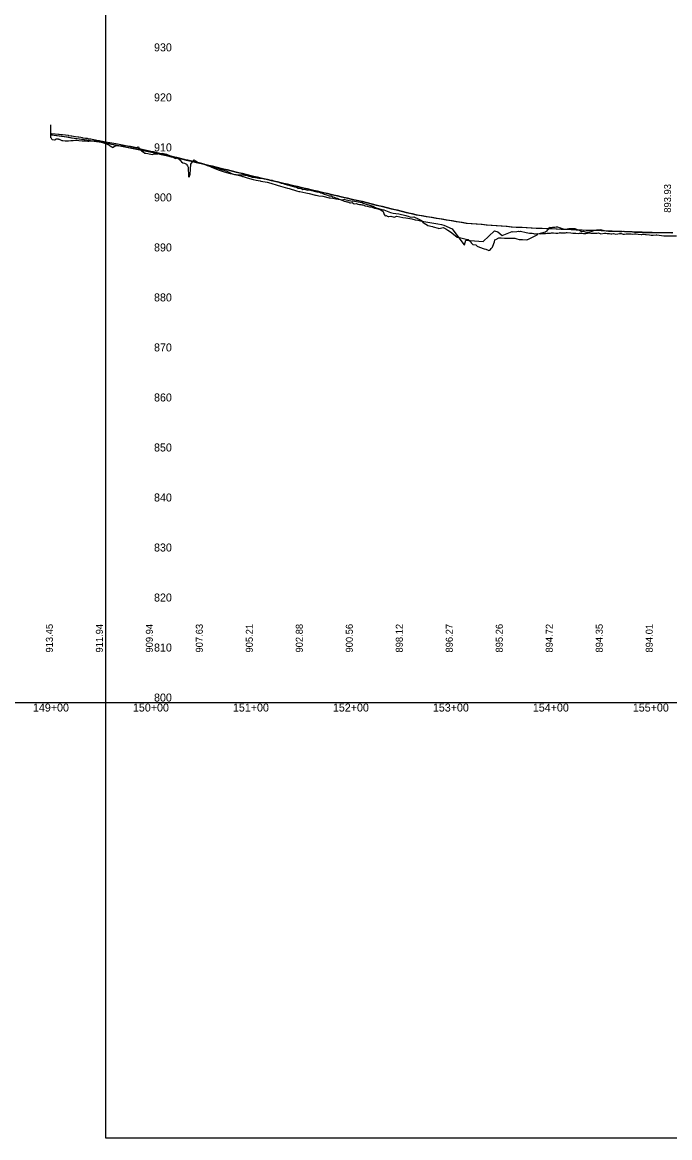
# Model space of a CAD drawing. Extents: x 1475774 to 1484571, y 1098511 to 1113011.
# Drawn here: x 1477639 to 1478287, y 1103076 to 1104191 of the extents above; entities that cross this region are included whole.
import ezdxf

# ---------------------------------------------------------------- set-up
doc = ezdxf.new("R2010")
doc.units = 0
for name, color, linetype in [('RD_DDB_ElevTX', 7, 'Continuous'), ('RD_DDB_PointTX', 7, 'Continuous'), ('RD_DDB_Profile_EX', 7, 'Continuous'), ('RD_DDB_Profile_Lbl', 7, 'Continuous'), ('RD_DDB_StaTX', 7, 'Continuous'), ('RD_DDB_StripGrade', 7, 'Continuous'), ('RD_GPK_Profile_Cell', 7, 'Continuous'), ('RD_Sketch2', 7, 'Continuous'), ('RD_Sketch3', 7, 'Continuous'), ('RD_Sketch5', 7, 'Continuous')]:
    doc.layers.add(name, color=color, linetype=linetype)

msp = doc.modelspace()

# ---------------------------------------------------------------- linework, layer by layer
at = {"layer": 'RD_DDB_PointTX'}
for points in [[(1477668.3, 1104079), (1477669.4, 1104078.9), (1477674.4, 1104078.1), (1477679.4, 1104077.4), (1477684.4, 1104076.7), (1477689.4, 1104075.9), (1477694.4, 1104075.2), (1477699.4, 1104074.4), (1477704.4, 1104073.7), (1477709.4, 1104072.9), (1477714.4, 1104072.2), (1477719.4, 1104071.4), (1477724.4, 1104070.4), (1477729.4, 1104069.4), (1477734.4, 1104068.4), (1477739.4, 1104067.4), (1477744.4, 1104066.4), (1477749.4, 1104065.4), (1477754.4, 1104064.4), (1477759.4, 1104063.4), (1477764.4, 1104062.4), (1477769.4, 1104061.5), (1477774.4, 1104060.4), (1477779.4, 1104059.2), (1477784.4, 1104058.1), (1477789.4, 1104056.9), (1477794.4, 1104055.8), (1477799.4, 1104054.6), (1477804.4, 1104053.4), (1477809.4, 1104052.3), (1477814.4, 1104051.1), (1477819.4, 1104050), (1477824.4, 1104048.8), (1477829.4, 1104047.6), (1477834.4, 1104046.4), (1477839.4, 1104045.2), (1477844.4, 1104044), (1477849.4, 1104042.7), (1477854.4, 1104041.5), (1477859.4, 1104040.3), (1477864.4, 1104039.1), (1477869.4, 1104037.9), (1477874.4, 1104036.7), (1477879.4, 1104035.5), (1477884.4, 1104034.4), (1477889.4, 1104033.2), (1477894.4, 1104032), (1477899.4, 1104030.9), (1477904.4, 1104029.7), (1477909.4, 1104028.5), (1477914.4, 1104027.4), (1477919.4, 1104026.2), (1477924.4, 1104025), (1477929.4, 1104023.9), (1477934.4, 1104022.7), (1477939.4, 1104021.6), (1477944.4, 1104020.4), (1477949.4, 1104019.2), (1477954.4, 1104018.1), (1477959.4, 1104016.9), (1477964.4, 1104015.8), (1477969.4, 1104014.6), (1477974.4, 1104013.5), (1477979.4, 1104012.3), (1477984.4, 1104011.1), (1477989.4, 1104009.9), (1477994.4, 1104008.6), (1477999.4, 1104007.4), (1478004.4, 1104006.2), (1478009.4, 1104004.9), (1478014.4, 1104003.7), (1478019.4, 1104002.5), (1478024.4, 1104001.2), (1478029.4, 1104000), (1478034.4, 1103998.9), (1478039.4, 1103998.1), (1478044.4, 1103997.2), (1478049.4, 1103996.4), (1478054.4, 1103995.5), (1478059.4, 1103994.7), (1478064.4, 1103993.8), (1478069.4, 1103993), (1478074.4, 1103992.1), (1478079.4, 1103991.3), (1478084.4, 1103990.6), (1478089.4, 1103990.2), (1478094.4, 1103989.8), (1478099.4, 1103989.3), (1478104.4, 1103988.9), (1478109.4, 1103988.5), (1478114.4, 1103988.1), (1478119.4, 1103987.7), (1478124.4, 1103987.3), (1478129.4, 1103986.9), (1478134.4, 1103986.6), (1478139.4, 1103986.3), (1478144.4, 1103986.1), (1478149.4, 1103985.9), (1478154.4, 1103985.6), (1478159.4, 1103985.4), (1478164.4, 1103985.2)], [(1478164.4, 1103985.2), (1478169.4, 1103985), (1478174.4, 1103984.7), (1478179.4, 1103984.5), (1478184.4, 1103984.3), (1478189.4, 1103984.1), (1478194.4, 1103983.9), (1478199.4, 1103983.8), (1478204.4, 1103983.6), (1478209.4, 1103983.4), (1478214.4, 1103983.3), (1478219.4, 1103983.1), (1478224.4, 1103982.9), (1478229.4, 1103982.8), (1478234.4, 1103982.6), (1478239.4, 1103982.4), (1478244.4, 1103982.2), (1478249.4, 1103982.1), (1478254.4, 1103981.9), (1478259.4, 1103981.7), (1478264.4, 1103981.5), (1478269.4, 1103981.4), (1478274.4, 1103981.2), (1478279.4, 1103981.1), (1478284.4, 1103981), (1478289.4, 1103980.9)]]:
    msp.add_lwpolyline(points, dxfattribs=at)
at = {"layer": 'RD_DDB_Profile_EX'}
for points in [[(1477668.3, 1104078.9), (1477668.5, 1104078.9), (1477673.5, 1104078.1), (1477678.5, 1104077.4), (1477683.5, 1104076.7), (1477688.5, 1104075.9), (1477693.5, 1104075.2), (1477698.5, 1104074.4), (1477703.5, 1104073.7), (1477708.5, 1104072.9), (1477713.5, 1104072.2), (1477718.5, 1104071.4), (1477723.5, 1104070.4), (1477728.5, 1104069.4), (1477733.5, 1104068.4), (1477738.5, 1104067.4), (1477743.5, 1104066.4), (1477748.5, 1104065.4), (1477753.5, 1104064.4), (1477758.5, 1104063.4), (1477763.5, 1104062.4), (1477768.5, 1104061.5), (1477773.5, 1104060.4), (1477778.5, 1104059.2), (1477783.5, 1104058.1), (1477788.5, 1104056.9), (1477793.5, 1104055.8), (1477798.5, 1104054.6), (1477803.5, 1104053.4), (1477808.5, 1104052.3), (1477813.5, 1104051.1), (1477818.5, 1104050), (1477823.5, 1104048.8), (1477828.5, 1104047.6), (1477833.5, 1104046.4), (1477838.5, 1104045.2), (1477843.5, 1104044), (1477848.5, 1104042.7), (1477853.5, 1104041.5), (1477858.5, 1104040.3), (1477863.5, 1104039.1), (1477868.5, 1104037.9), (1477873.5, 1104036.7), (1477878.5, 1104035.5), (1477883.5, 1104034.4), (1477888.5, 1104033.2), (1477893.5, 1104032), (1477898.5, 1104030.9), (1477903.5, 1104029.7), (1477908.5, 1104028.5), (1477913.5, 1104027.4), (1477918.5, 1104026.2), (1477923.5, 1104025), (1477928.5, 1104023.9), (1477933.5, 1104022.7), (1477938.5, 1104021.6), (1477943.5, 1104020.4), (1477948.5, 1104019.2), (1477953.5, 1104018.1), (1477958.5, 1104016.9), (1477963.5, 1104015.8), (1477968.5, 1104014.6), (1477973.5, 1104013.5), (1477978.5, 1104012.3), (1477983.5, 1104011.1), (1477988.5, 1104009.9), (1477993.5, 1104008.6), (1477998.5, 1104007.4), (1478003.5, 1104006.2), (1478008.5, 1104004.9), (1478013.5, 1104003.7), (1478018.5, 1104002.5), (1478023.5, 1104001.2), (1478028.5, 1104000), (1478033.5, 1103998.9), (1478038.5, 1103998.1), (1478043.5, 1103997.2), (1478048.5, 1103996.4), (1478053.5, 1103995.5), (1478058.5, 1103994.7), (1478063.5, 1103993.8), (1478068.5, 1103993), (1478073.5, 1103992.1), (1478078.5, 1103991.3), (1478083.5, 1103990.6), (1478088.5, 1103990.2), (1478093.5, 1103989.8), (1478098.5, 1103989.3), (1478103.5, 1103988.9), (1478108.5, 1103988.5), (1478113.5, 1103988.1), (1478118.5, 1103987.7), (1478123.5, 1103987.3), (1478128.5, 1103986.9), (1478133.5, 1103986.6), (1478138.5, 1103986.3), (1478143.5, 1103986.1), (1478148.5, 1103985.9), (1478153.5, 1103985.6), (1478158.5, 1103985.4), (1478163.5, 1103985.2)], [(1478163.5, 1103985.2), (1478168.5, 1103985), (1478173.5, 1103984.7), (1478178.5, 1103984.5), (1478183.5, 1103984.3), (1478188.5, 1103984.1), (1478193.5, 1103983.9), (1478198.5, 1103983.8), (1478203.5, 1103983.6), (1478208.5, 1103983.4), (1478213.5, 1103983.3), (1478218.5, 1103983.1), (1478223.5, 1103982.9), (1478228.5, 1103982.8), (1478233.5, 1103982.6), (1478238.5, 1103982.4), (1478243.5, 1103982.2), (1478248.5, 1103982.1), (1478253.5, 1103981.9), (1478258.5, 1103981.7), (1478263.5, 1103981.5), (1478268.5, 1103981.4), (1478273.5, 1103981.2), (1478278.5, 1103981.1), (1478283.5, 1103981), (1478288.5, 1103980.9)]]:
    msp.add_lwpolyline(points, dxfattribs=at)
at = {"layer": 'RD_GPK_Profile_Cell'}
msp.add_line((1477571, 1103511.2), (1484571, 1103511.2), dxfattribs=at)
at = {"layer": 'RD_Sketch2'}
msp.add_lwpolyline([(1477667.5, 1104080.2), (1477668, 1104080.2), (1477668.8, 1104080.1), (1477672.2, 1104079.8), (1477675.6, 1104079.4), (1477676.2, 1104079.4), (1477677.9, 1104079.2), (1477679, 1104079.1), (1477679.6, 1104079.1), (1477682.5, 1104078.7), (1477685.4, 1104078.3), (1477685.8, 1104078.2), (1477688.4, 1104077.8), (1477689.1, 1104077.7), (1477690.8, 1104077.3), (1477692.5, 1104077.1), (1477695.2, 1104076.6), (1477695.9, 1104076.6), (1477698, 1104076.3), (1477699.3, 1104076.1), (1477700, 1104075.9), (1477702.7, 1104075.5), (1477703.2, 1104075.4), (1477704.3, 1104075.3), (1477706.1, 1104074.9), (1477708.1, 1104074.6), (1477709.4, 1104074.3), (1477712.8, 1104073.7), (1477714.1, 1104073.5), (1477716.2, 1104073.1), (1477717.2, 1104072.9), (1477719.6, 1104072.5), (1477723, 1104071.9), (1477723.4, 1104071.8), (1477726.3, 1104071.2), (1477726.9, 1104071.1), (1477733.1, 1104070), (1477734.5, 1104069.8), (1477741.3, 1104068.3), (1477744.4, 1104067.8), (1477751.6, 1104066.2), (1477753.6, 1104065.7), (1477756.7, 1104065.1), (1477759.4, 1104064.4), (1477766.8, 1104062.7), (1477768, 1104062.5), (1477770.5, 1104062), (1477778, 1104060.2), (1477778.9, 1104060), (1477783.1, 1104059), (1477785.3, 1104058.3), (1477793.1, 1104056.5), (1477793.8, 1104056.3), (1477801.3, 1104054.5), (1477804, 1104053.9), (1477805.1, 1104053.6), (1477811.7, 1104052), (1477812.1, 1104052), (1477812.7, 1104051.9), (1477813.3, 1104051.8), (1477814, 1104051.6), (1477814.8, 1104051.4), (1477820.9, 1104049.6), (1477821.6, 1104049.4), (1477822.5, 1104049.1), (1477824.5, 1104048.2), (1477826.7, 1104047.5), (1477827.1, 1104047.4), (1477827.4, 1104047.4), (1477827.7, 1104047.4), (1477830.3, 1104046.8), (1477830.7, 1104046.7), (1477831.4, 1104046.4), (1477832.4, 1104046.2), (1477833.5, 1104045.8), (1477834.7, 1104045.4), (1477836.5, 1104044.9), (1477837.5, 1104044.5), (1477838.5, 1104044.2), (1477839.7, 1104043.7), (1477840.9, 1104043.3), (1477841.2, 1104043.4), (1477841.6, 1104043.3), (1477842, 1104043), (1477842.9, 1104042.7), (1477843.9, 1104042.4), (1477845.5, 1104041.8), (1477847, 1104041), (1477848.1, 1104040.5), (1477848.7, 1104040.2), (1477850.8, 1104039.4), (1477851.8, 1104039.2), (1477853.5, 1104039), (1477855.8, 1104038.9), (1477857.8, 1104038.7), (1477859.3, 1104038.9), (1477860, 1104038.8), (1477860.8, 1104038.7), (1477862.1, 1104038.4), (1477863.1, 1104038.3), (1477864.2, 1104038.1), (1477865.9, 1104037.5), (1477866.4, 1104037.4), (1477866.8, 1104037.4), (1477869.5, 1104036.6), (1477870.5, 1104036.4), (1477870.9, 1104036.3), (1477872.8, 1104036), (1477874.3, 1104035.7), (1477875.9, 1104035.4), (1477878, 1104035.3), (1477879.3, 1104035.4), (1477881, 1104035), (1477881.4, 1104034.9), (1477881.7, 1104034.8), (1477883.5, 1104034.5), (1477886, 1104033.9), (1477887.8, 1104033.6), (1477889.2, 1104033.3), (1477890, 1104033.2), (1477891, 1104032.8), (1477892.1, 1104032.4), (1477892.9, 1104032.2), (1477894.3, 1104032), (1477896.1, 1104031.3), (1477896.7, 1104031.1), (1477898.5, 1104030.6), (1477900.7, 1104030.1), (1477901.1, 1104029.9), (1477904.2, 1104028.9), (1477906.1, 1104028.3), (1477907.1, 1104028.2), (1477907.9, 1104027.9), (1477909.3, 1104027.6), (1477911.6, 1104026.8), (1477913.6, 1104026.3), (1477915.4, 1104025.6), (1477916.2, 1104025.5), (1477917.9, 1104025.2), (1477919.1, 1104024.7), (1477920, 1104024.2), (1477921.2, 1104024.3), (1477922.8, 1104024), (1477924.3, 1104023.5), (1477926.6, 1104023.7), (1477928.6, 1104023), (1477930.3, 1104022.8), (1477931.3, 1104022.6), (1477934, 1104021.9), (1477935, 1104021.8), (1477936.3, 1104021.5), (1477937.2, 1104021.2), (1477937.8, 1104020.9), (1477939.3, 1104020.4), (1477941.5, 1104019.6), (1477943.6, 1104018.9), (1477945.3, 1104018.1), (1477946.4, 1104017.8), (1477947.9, 1104017.7), (1477949, 1104017.3), (1477950, 1104016.9), (1477951.4, 1104016.3), (1477952.2, 1104016), (1477952.7, 1104015.8), (1477954.3, 1104015.3), (1477956.5, 1104014.3), (1477960.2, 1104013.1), (1477960.7, 1104012.8), (1477961.5, 1104012.5), (1477962.9, 1104012.2), (1477963.9, 1104011.8), (1477965, 1104011.7), (1477966.5, 1104011), (1477967.2, 1104010.9), (1477967.7, 1104010.9), (1477969.3, 1104011), (1477971.5, 1104009.9), (1477973.6, 1104010.1), (1477975.1, 1104009.6), (1477976.6, 1104009.2), (1477977.9, 1104009.1), (1477978.9, 1104008.8), (1477980, 1104008.8), (1477981.6, 1104008), (1477982.2, 1104007.8), (1477982.6, 1104007.7), (1477984.3, 1104007.6), (1477986.6, 1104006.7), (1477988.6, 1104006.7), (1477990.1, 1104006), (1477991.7, 1104005.6), (1477993.6, 1104005.1), (1477994, 1104005), (1477995.9, 1104004.4), (1477998, 1104003.8), (1478000.4, 1104002.1), (1478001.3, 1103999.1), (1478002.3, 1103997.8), (1478003.8, 1103998.1), (1478004.4, 1103997.6), (1478005.3, 1103997.2), (1478006.2, 1103997), (1478008.1, 1103997.3), (1478011.4, 1103996.5), (1478014, 1103997.3), (1478020.1, 1103996.1), (1478023, 1103995.9), (1478029.2, 1103994.7), (1478032.4, 1103993.8), (1478032.8, 1103993.7), (1478035.2, 1103993.3), (1478039, 1103992.3), (1478045.2, 1103991.3), (1478049, 1103990.8), (1478055.2, 1103989.8), (1478058.8, 1103989), (1478061.2, 1103988.6), (1478069.5, 1103984.9), (1478081, 1103969), (1478081.7, 1103968.8), (1478083, 1103973.6), (1478100.3, 1103972.1), (1478111.8, 1103982.7), (1478115, 1103981.9), (1478119.5, 1103978), (1478129.3, 1103982.2), (1478129.8, 1103981.9), (1478134, 1103982.1), (1478135.6, 1103982.4), (1478136.9, 1103982.2), (1478137.9, 1103982.4), (1478143.3, 1103981.2), (1478146.8, 1103980.3), (1478147.1, 1103980.3), (1478147.6, 1103980.3), (1478149.4, 1103980.4), (1478150.8, 1103980.1), (1478151.6, 1103979.9), (1478152.7, 1103979.8), (1478154.5, 1103980.1), (1478158.2, 1103979.7), (1478160.2, 1103980.2), (1478162, 1103980), (1478162.3, 1103980.1), (1478162.8, 1103980), (1478164.5, 1103980.3), (1478165.7, 1103980.3), (1478166.6, 1103980.5), (1478167.8, 1103980.5), (1478168.7, 1103980.9), (1478169.4, 1103980.9), (1478170.9, 1103980.9), (1478173.2, 1103980.3), (1478175.2, 1103980.6), (1478176.9, 1103980.9), (1478177.3, 1103981), (1478177.9, 1103980.9), (1478179.5, 1103980.9), (1478180.6, 1103980.8), (1478181.6, 1103980.9), (1478182.9, 1103980.9), (1478183.8, 1103981), (1478184.4, 1103981.1), (1478188.1, 1103980.9), (1478190.2, 1103980.5), (1478191.9, 1103980.4), (1478193, 1103980.3), (1478195.6, 1103980.2), (1478196.6, 1103980.4), (1478198, 1103980.4), (1478198.8, 1103980.4), (1478199.3, 1103980.4), (1478200.9, 1103980.1), (1478203.1, 1103980.2), (1478206.8, 1103980.7), (1478208.1, 1103980.6), (1478209.5, 1103980.5), (1478210.5, 1103980.5), (1478211.6, 1103980.4), (1478213.1, 1103980.3), (1478214.3, 1103980.4), (1478215.9, 1103980.7), (1478218.1, 1103979.9), (1478221.7, 1103980.5), (1478223.2, 1103980.5), (1478224.5, 1103980.2), (1478225.5, 1103980.1), (1478226.6, 1103980), (1478228.2, 1103979.8), (1478229.2, 1103979.8), (1478230.9, 1103980), (1478233.2, 1103979.6), (1478235.2, 1103979.9), (1478236.7, 1103980.2), (1478238.3, 1103980.1), (1478240.4, 1103979.4), (1478241.7, 1103979.5), (1478243.3, 1103979.7), (1478243.8, 1103979.8), (1478244.2, 1103979.8), (1478245.9, 1103979.8), (1478247.9, 1103979.8), (1478248.3, 1103979.8), (1478250.2, 1103979.5), (1478251.6, 1103979.7), (1478252.4, 1103979.8), (1478253.4, 1103979.7), (1478255.4, 1103979.4), (1478258.4, 1103979.1), (1478259.1, 1103979.1), (1478261, 1103979.5), (1478262.8, 1103979.1), (1478263.4, 1103979.1), (1478266.6, 1103978.9), (1478268.5, 1103978.6), (1478269.5, 1103978.5), (1478270.3, 1103978.5), (1478273.5, 1103978.7), (1478274.1, 1103978.7), (1478281.2, 1103977.8), (1478282.8, 1103977.7), (1478293.7, 1103977.9)], dxfattribs=at)
at = {"layer": 'RD_Sketch3'}
msp.add_lwpolyline([(1477667.5, 1104088.8), (1477667.6, 1104075.7), (1477667.9, 1104076.1), (1477668.8, 1104074.7), (1477669.3, 1104074), (1477671.6, 1104073.6), (1477672.2, 1104073.9), (1477673.4, 1104074.6), (1477675.3, 1104074.6), (1477675.6, 1104074.5), (1477676.2, 1104074.4), (1477678.4, 1104073.4), (1477679, 1104073.2), (1477680, 1104073), (1477682.4, 1104072.9), (1477684.8, 1104072.7), (1477685.8, 1104072.7), (1477688.1, 1104073.1), (1477689.1, 1104073.1), (1477690.2, 1104073.2), (1477692.5, 1104073.4), (1477693.9, 1104073.5), (1477696, 1104073), (1477699.4, 1104072.9), (1477702.7, 1104072.6), (1477705, 1104072.4), (1477706.1, 1104072.5), (1477707.3, 1104072.7), (1477708.2, 1104072.7), (1477709.4, 1104072.7), (1477712.8, 1104072.7), (1477714.7, 1104072.7), (1477715.3, 1104072.5), (1477716.2, 1104072.2), (1477716.9, 1104071.7), (1477719.6, 1104071), (1477721.5, 1104070.5), (1477723, 1104069.9), (1477724.3, 1104069.3), (1477726.3, 1104068.3), (1477726.8, 1104068.1), (1477727.4, 1104067.9), (1477729.1, 1104066.6), (1477729.6, 1104066.2), (1477730.3, 1104066.3), (1477731.7, 1104067.4), (1477732.9, 1104067.9), (1477733.4, 1104068), (1477735, 1104068), (1477735.7, 1104067.9), (1477740.5, 1104068), (1477742.1, 1104068), (1477747.6, 1104067.4), (1477749, 1104067.2), (1477749.4, 1104067.2), (1477753.7, 1104066.2), (1477755.3, 1104066.7), (1477755.6, 1104066.7), (1477756.8, 1104064.7), (1477758.7, 1104062.8), (1477759.7, 1104062), (1477760.2, 1104061.7), (1477762, 1104060.5), (1477763.1, 1104060.3), (1477765.1, 1104060), (1477769.3, 1104059.2), (1477771.5, 1104059.7), (1477774.9, 1104059.8), (1477776.5, 1104060), (1477776.9, 1104060), (1477779.2, 1104060.3), (1477783.6, 1104059.5), (1477784.4, 1104059.2), (1477785.9, 1104058.5), (1477792.6, 1104055), (1477794.7, 1104055.6), (1477796.9, 1104053.8), (1477798.8, 1104051.7), (1477799.9, 1104050.9), (1477801.8, 1104050.4), (1477802.9, 1104049.8), (1477803.6, 1104049.4), (1477803.9, 1104048.9), (1477804.7, 1104047.7), (1477805.3, 1104046.4), (1477805.8, 1104037.1), (1477806.3, 1104036.6), (1477806.8, 1104037.5), (1477807.3, 1104039.5), (1477808, 1104049.4), (1477809.7, 1104051.6), (1477811.3, 1104053.6), (1477811.9, 1104053.1), (1477812.7, 1104052.7), (1477813.4, 1104052.4), (1477814.2, 1104051.8), (1477814.8, 1104051.5), (1477815.5, 1104051), (1477816.1, 1104050.9), (1477817.4, 1104050.7), (1477818.6, 1104050.3), (1477820.8, 1104049.6), (1477826.9, 1104047.7), (1477827.5, 1104047.5), (1477829, 1104046.5), (1477829.7, 1104046.1), (1477833.7, 1104044.3), (1477836.4, 1104043.3), (1477837.3, 1104043.1), (1477841.2, 1104041.9), (1477847.2, 1104040.2), (1477847.9, 1104040), (1477852.3, 1104039.2), (1477858, 1104037.7), (1477859.6, 1104037.2), (1477860.2, 1104037), (1477864.3, 1104035.9), (1477870.2, 1104034.1), (1477870.5, 1104034), (1477873.4, 1104033.5), (1477877.5, 1104032.8), (1477878.1, 1104032.6), (1477884.2, 1104031.6), (1477887.9, 1104030.5), (1477894.4, 1104028.6), (1477897.7, 1104027.6), (1477904.6, 1104025.6), (1477906.2, 1104025.1), (1477913.7, 1104022.8), (1477916.1, 1104022.1), (1477916.9, 1104022), (1477923.1, 1104020.7), (1477926.2, 1104020), (1477932.7, 1104018.6), (1477933.5, 1104018.5), (1477936.1, 1104017.9), (1477939.9, 1104017.3), (1477946.5, 1104015.9), (1477947.5, 1104015.7), (1477950, 1104015.3), (1477953, 1104014.9), (1477959.9, 1104013.7), (1477961.6, 1104014.5), (1477962, 1104014), (1477969.4, 1104012.6), (1477969.8, 1104012.7), (1477979.4, 1104011), (1477980.5, 1104010.5), (1477984.4, 1104009.1), (1477990.3, 1104007.3), (1477991.8, 1104006.6), (1477994.5, 1104005.5), (1477998.2, 1104004.5), (1478000.7, 1104003.9), (1478001.2, 1104003.8), (1478007.6, 1104001.1), (1478010.3, 1104000.6), (1478013.2, 1104000.2), (1478016.2, 1103999.7), (1478022.9, 1103998.1), (1478024.1, 1103997.7), (1478025.4, 1103997.3), (1478027.8, 1103996.6), (1478031, 1103996.9), (1478035.9, 1103994.6), (1478038.7, 1103993.1), (1478039.3, 1103992.5), (1478040.1, 1103991.5), (1478041.7, 1103990.1), (1478042.8, 1103989.8), (1478045.2, 1103988), (1478049.8, 1103987), (1478050.5, 1103986.8), (1478055.3, 1103985.3), (1478056, 1103985.1), (1478060.6, 1103986), (1478061.1, 1103985.9), (1478063.1, 1103984.9), (1478065.2, 1103983.6), (1478065.8, 1103983.2), (1478069, 1103980.8), (1478074.5, 1103976.6), (1478075.4, 1103976.4), (1478083.4, 1103974.6), (1478085.4, 1103974.1), (1478087.9, 1103971.8), (1478088.5, 1103970.7), (1478089.9, 1103969.1), (1478093.1, 1103968.7), (1478094.3, 1103967.3), (1478096.7, 1103966.5), (1478101.3, 1103964.7), (1478102.9, 1103964.4), (1478105.3, 1103963.3), (1478106.2, 1103963), (1478106.6, 1103963.3), (1478107.8, 1103964), (1478108.4, 1103965.1), (1478109.6, 1103966.5), (1478110.2, 1103967.6), (1478111.7, 1103971.7), (1478112.2, 1103973.9), (1478112.9, 1103974.1), (1478115.9, 1103975.8), (1478118.3, 1103975.8), (1478121.9, 1103975.5), (1478123.9, 1103975.3), (1478131.2, 1103975.5), (1478132.1, 1103975.4), (1478134, 1103974.9), (1478136.5, 1103974.2), (1478139.9, 1103974.1), (1478144, 1103973.9), (1478144.6, 1103974), (1478145.1, 1103974.2), (1478154.3, 1103978.9), (1478155, 1103979.7), (1478157.7, 1103980.4), (1478162.7, 1103981.8), (1478164.4, 1103983.2), (1478165.6, 1103984.5), (1478166.8, 1103986.6), (1478168.1, 1103986.2), (1478169.9, 1103986.3), (1478172.2, 1103986.3), (1478173.4, 1103986.7), (1478174.7, 1103986.8), (1478176.4, 1103986.2), (1478177.4, 1103985.9), (1478177.7, 1103985.8), (1478179.4, 1103985.1), (1478181.5, 1103984.3), (1478184.4, 1103984.7), (1478185.4, 1103984.8), (1478186.5, 1103985), (1478187.4, 1103985), (1478190.9, 1103985.1), (1478192, 1103985.1), (1478192.8, 1103984.8), (1478195.3, 1103983.9), (1478196, 1103983.8), (1478196.9, 1103983.6), (1478197.9, 1103982.8), (1478198.7, 1103982.2), (1478200.6, 1103982.4), (1478202.3, 1103981.7), (1478203.6, 1103981.3), (1478205.2, 1103981.3), (1478207.2, 1103981.8), (1478209.5, 1103982.4), (1478211.7, 1103983.3), (1478213.8, 1103983.8), (1478217.7, 1103984), (1478221.9, 1103983), (1478224, 1103982.8), (1478225.7, 1103982.5), (1478226.7, 1103982.4), (1478228.3, 1103982.5), (1478229.4, 1103982.4), (1478230.4, 1103982.4), (1478231.8, 1103982.3), (1478232.6, 1103982.3), (1478233.1, 1103982.3), (1478234.7, 1103982.4), (1478236.9, 1103982.2), (1478239, 1103982.2), (1478240.6, 1103982.3), (1478241.1, 1103982.3), (1478241.8, 1103982.2), (1478243.3, 1103982), (1478244.4, 1103982.1), (1478245.4, 1103982.1), (1478246.9, 1103982.1), (1478247.6, 1103982.1), (1478248.1, 1103982), (1478249.7, 1103981.7), (1478251.9, 1103981.6), (1478255.6, 1103981.5), (1478256.1, 1103981.5), (1478256.9, 1103981.4), (1478259.3, 1103981.2), (1478262, 1103981), (1478263, 1103981.1), (1478266.2, 1103981.1), (1478267, 1103981.1), (1478269, 1103981.1), (1478270.5, 1103981.2), (1478272, 1103981.1), (1478273.3, 1103981), (1478274.3, 1103981), (1478275.4, 1103981.2), (1478277.1, 1103981.1), (1478278, 1103981), (1478280.7, 1103981.1), (1478281.7, 1103981), (1478282.1, 1103981.1), (1478282.9, 1103981), (1478286.6, 1103981.2), (1478290.2, 1103981.2)], dxfattribs=at)
at = {"layer": 'RD_Sketch5'}
msp.add_lwpolyline([(1477722.7, 1103076.2), (1481322.7, 1103076.2), (1481322.7, 1105276.2), (1477722.7, 1105276.2)], close=True, dxfattribs=at)

# ---------------------------------------------------------------- texts
at = {"layer": 'RD_DDB_ElevTX'}
for s, p in [('930', (1477771.2, 1104162.2)), ('920', (1477771.2, 1104112.2)), ('910', (1477771.2, 1104062.2)), ('900', (1477771.2, 1104012.2)), ('890', (1477771.2, 1103962.2)), ('880', (1477771.2, 1103912.2)), ('870', (1477771.2, 1103862.2)), ('860', (1477771.2, 1103812.2)), ('850', (1477771.2, 1103762.2)), ('840', (1477771.2, 1103712.2)), ('830', (1477771.2, 1103662.2)), ('820', (1477771.2, 1103612.2)), ('810', (1477771.2, 1103562.2)), ('800', (1477771.2, 1103512.2))]:
    msp.add_text(s, height=8, dxfattribs=at).set_placement(p)
at = {"layer": 'RD_DDB_Profile_Lbl'}
msp.add_text('893.93', height=7, rotation=90, dxfattribs=at).set_placement((1478288.3, 1104000.9))
at = {"layer": 'RD_DDB_StaTX'}
for s, p in [('149+00', (1477650.1, 1103502.2)), ('150+00', (1477750.1, 1103502.2)), ('151+00', (1477850.1, 1103502.2)), ('152+00', (1477950.1, 1103502.2)), ('153+00', (1478050.1, 1103502.2)), ('154+00', (1478150.1, 1103502.2)), ('155+00', (1478250.1, 1103502.2))]:
    msp.add_text(s, height=8, dxfattribs=at).set_placement(p)
at = {"layer": 'RD_DDB_StripGrade'}
for s, p in [('913.45', (1477670, 1103561.2)), ('911.94', (1477720, 1103561.2)), ('909.94', (1477770, 1103561.2)), ('907.63', (1477820, 1103561.2)), ('905.21', (1477870, 1103561.2)), ('902.88', (1477920, 1103561.2)), ('900.56', (1477970, 1103561.2)), ('898.12', (1478020, 1103561.2)), ('896.27', (1478070, 1103561.2)), ('895.26', (1478120, 1103561.2)), ('894.72', (1478170, 1103561.2)), ('894.35', (1478220, 1103561.2)), ('894.01', (1478270, 1103561.2))]:
    msp.add_text(s, height=7, rotation=90, dxfattribs=at).set_placement(p)

doc.saveas('drawing.dxf')
